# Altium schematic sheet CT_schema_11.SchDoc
size 281 x 153 mm
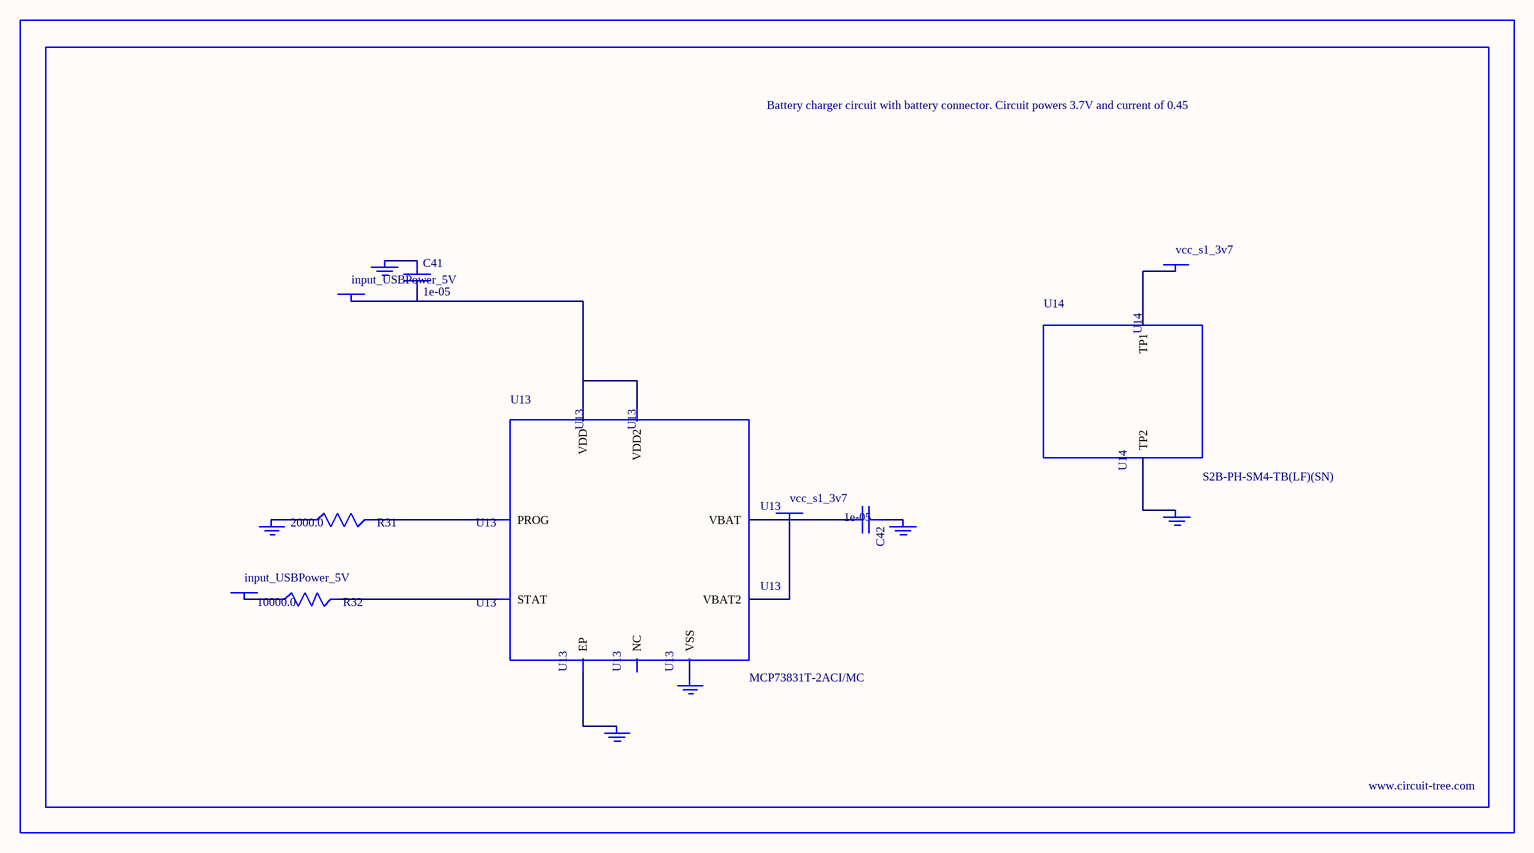
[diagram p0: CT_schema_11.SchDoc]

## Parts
BORDER10  (no value)
C41  1e-05  [C1206]
C42  1e-05  [C1206]
GND_INSTANCE_10_0  (no value)
GND_INSTANCE_10_1  (no value)
GND_INSTANCE_10_2  (no value)
GND_INSTANCE_10_3  (no value)
GND_INSTANCE_10_4  (no value)
GND_INSTANCE_10_5  (no value)
POWER_INSTANCE_10_0  input_USBPower_5V
POWER_INSTANCE_10_1  input_USBPower_5V
POWER_INSTANCE_10_2  vcc_s1_3v7
POWER_INSTANCE_10_3  vcc_s1_3v7
R31  2000.0  [R0603]
R32  10000.0  [R0603]
U13  MCP73831T-2ACI/MC  [DFN8_2X3MC]
U14  S2B-PH-SM4-TB(LF)(SN)  [JST-2-SMD]

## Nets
NetC41_1: C41.1 GND_INSTANCE_10_0.0(GND)
NetC41_2: C41.2 POWER_INSTANCE_10_0.0(PWR) U13.1(VDD) U13.2(VDD2)
NetC42_1: C42.1 GND_INSTANCE_10_1.0(GND)
NetC42_2: C42.2 POWER_INSTANCE_10_2.0(PWR) U13.3(VBAT) U13.4(VBAT2)
NetGND_INSTANCE_10_2_0: GND_INSTANCE_10_2.0(GND) R31.1
NetGND_INSTANCE_10_3_0: GND_INSTANCE_10_3.0(GND) U13.9(EP)
NetGND_INSTANCE_10_4_0: GND_INSTANCE_10_4.0(GND) U13.6(VSS)
NetGND_INSTANCE_10_5_0: GND_INSTANCE_10_5.0(GND) U14.2(TP2)
NetPOWER_INSTANCE_10_1_0: POWER_INSTANCE_10_1.0(PWR) R32.1
NetPOWER_INSTANCE_10_3_0: POWER_INSTANCE_10_3.0(PWR) U14.1(TP1)
NetR31_2: R31.2 U13.8(PROG)
NetR32_2: R32.2 U13.5(STAT)

Not connected (* = marked no-connect by the designer): U13 7(NC)

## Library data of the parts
BORDER10 = BORDER_PAGE10
C41 C42 = C1206C106K3RACTU
GND_INSTANCE_10_0-GND_INSTANCE_10_5 = GND
POWER_INSTANCE_10_0-POWER_INSTANCE_10_3 = PWR
R31 = RC0603JR-072KL
R32 = RC0603JR-0710KL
